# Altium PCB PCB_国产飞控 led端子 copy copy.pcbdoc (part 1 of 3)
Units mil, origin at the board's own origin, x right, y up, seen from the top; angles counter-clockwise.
Board outline 3467.18 x 2997.13 mil, 4 copper layers (Top Layer, Inner1, Inner2, Bottom Layer), stack 2.757 mil thick; 107 components, 163 nets, 527 pads, 148 vias.
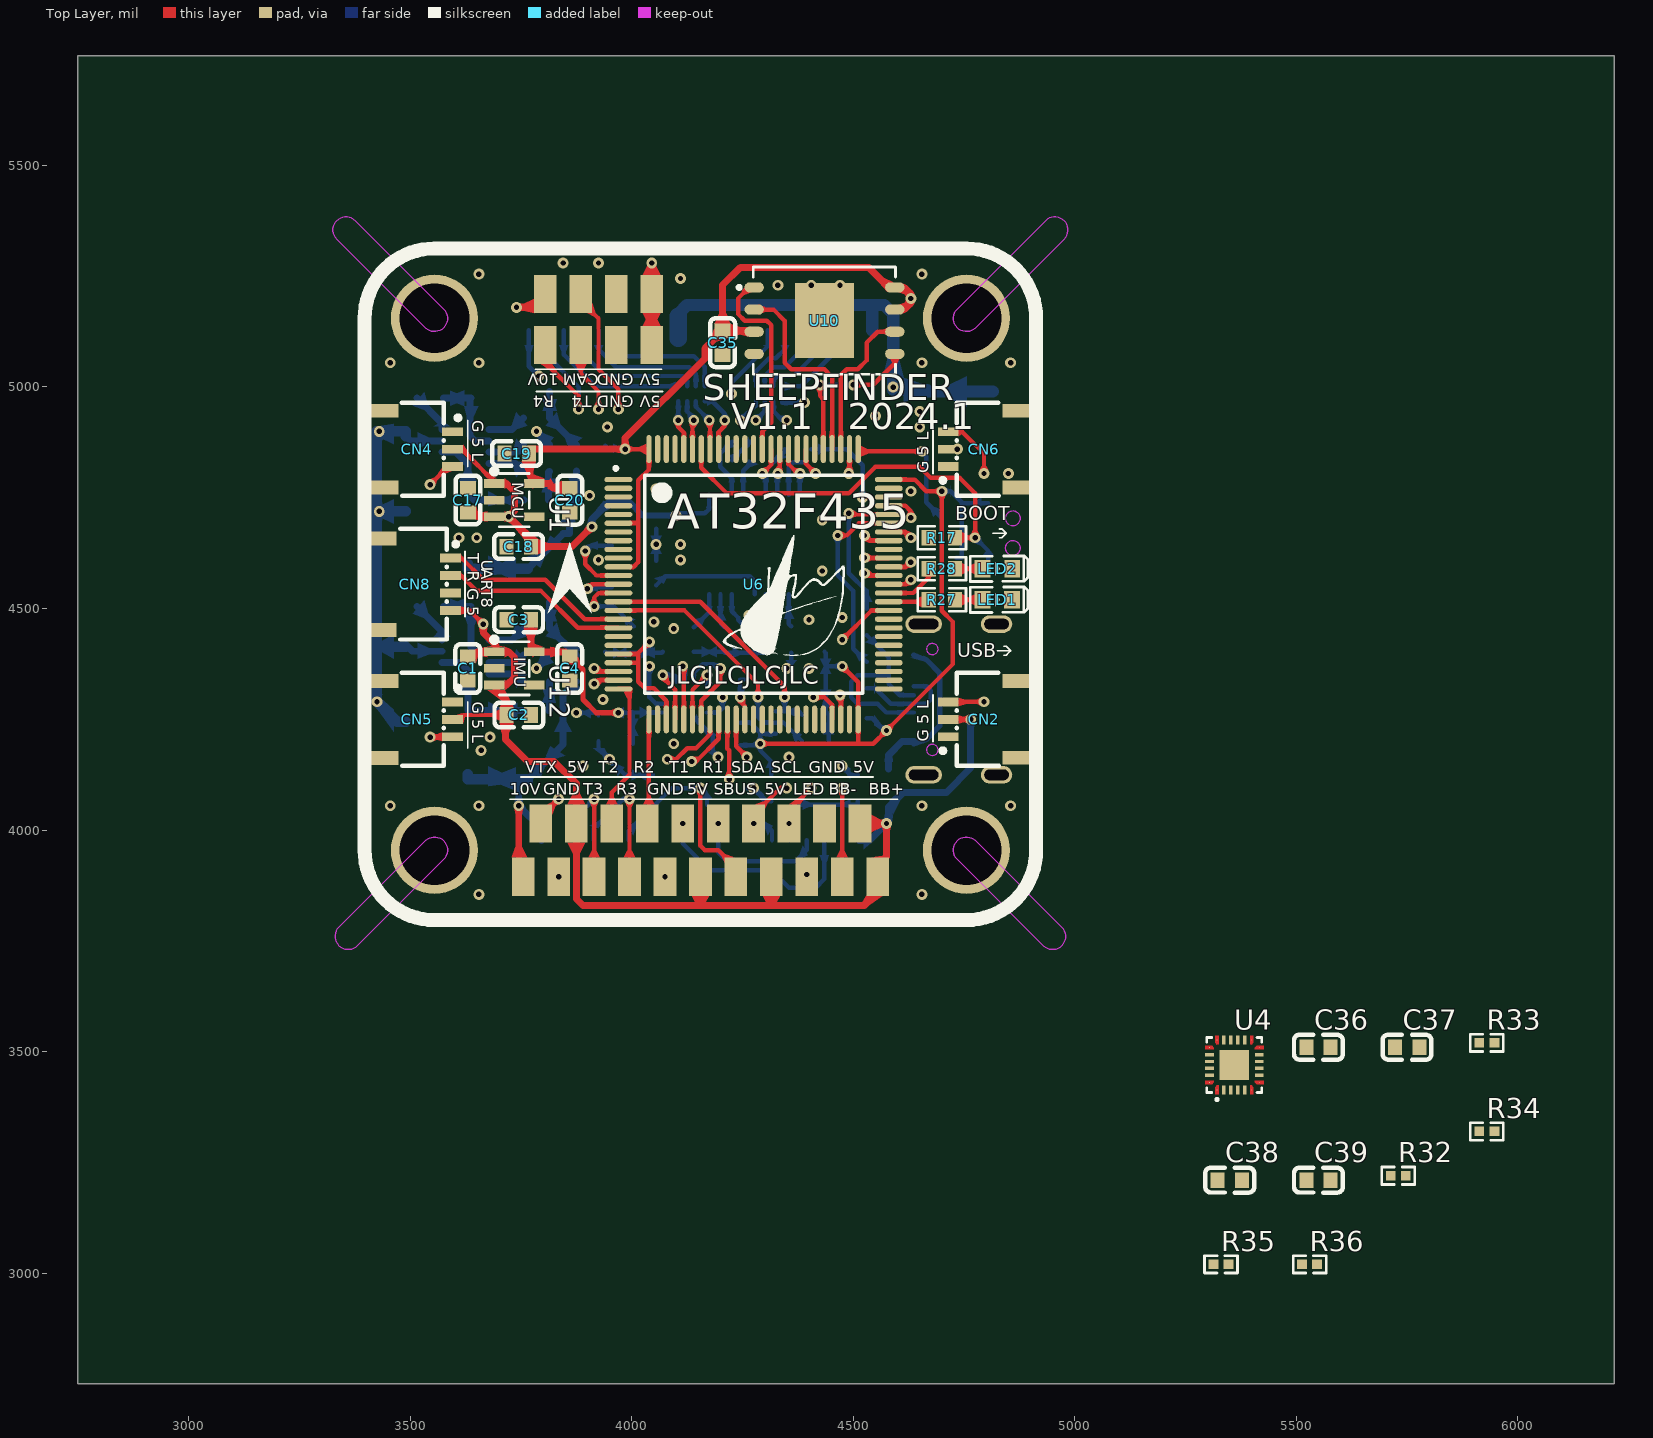
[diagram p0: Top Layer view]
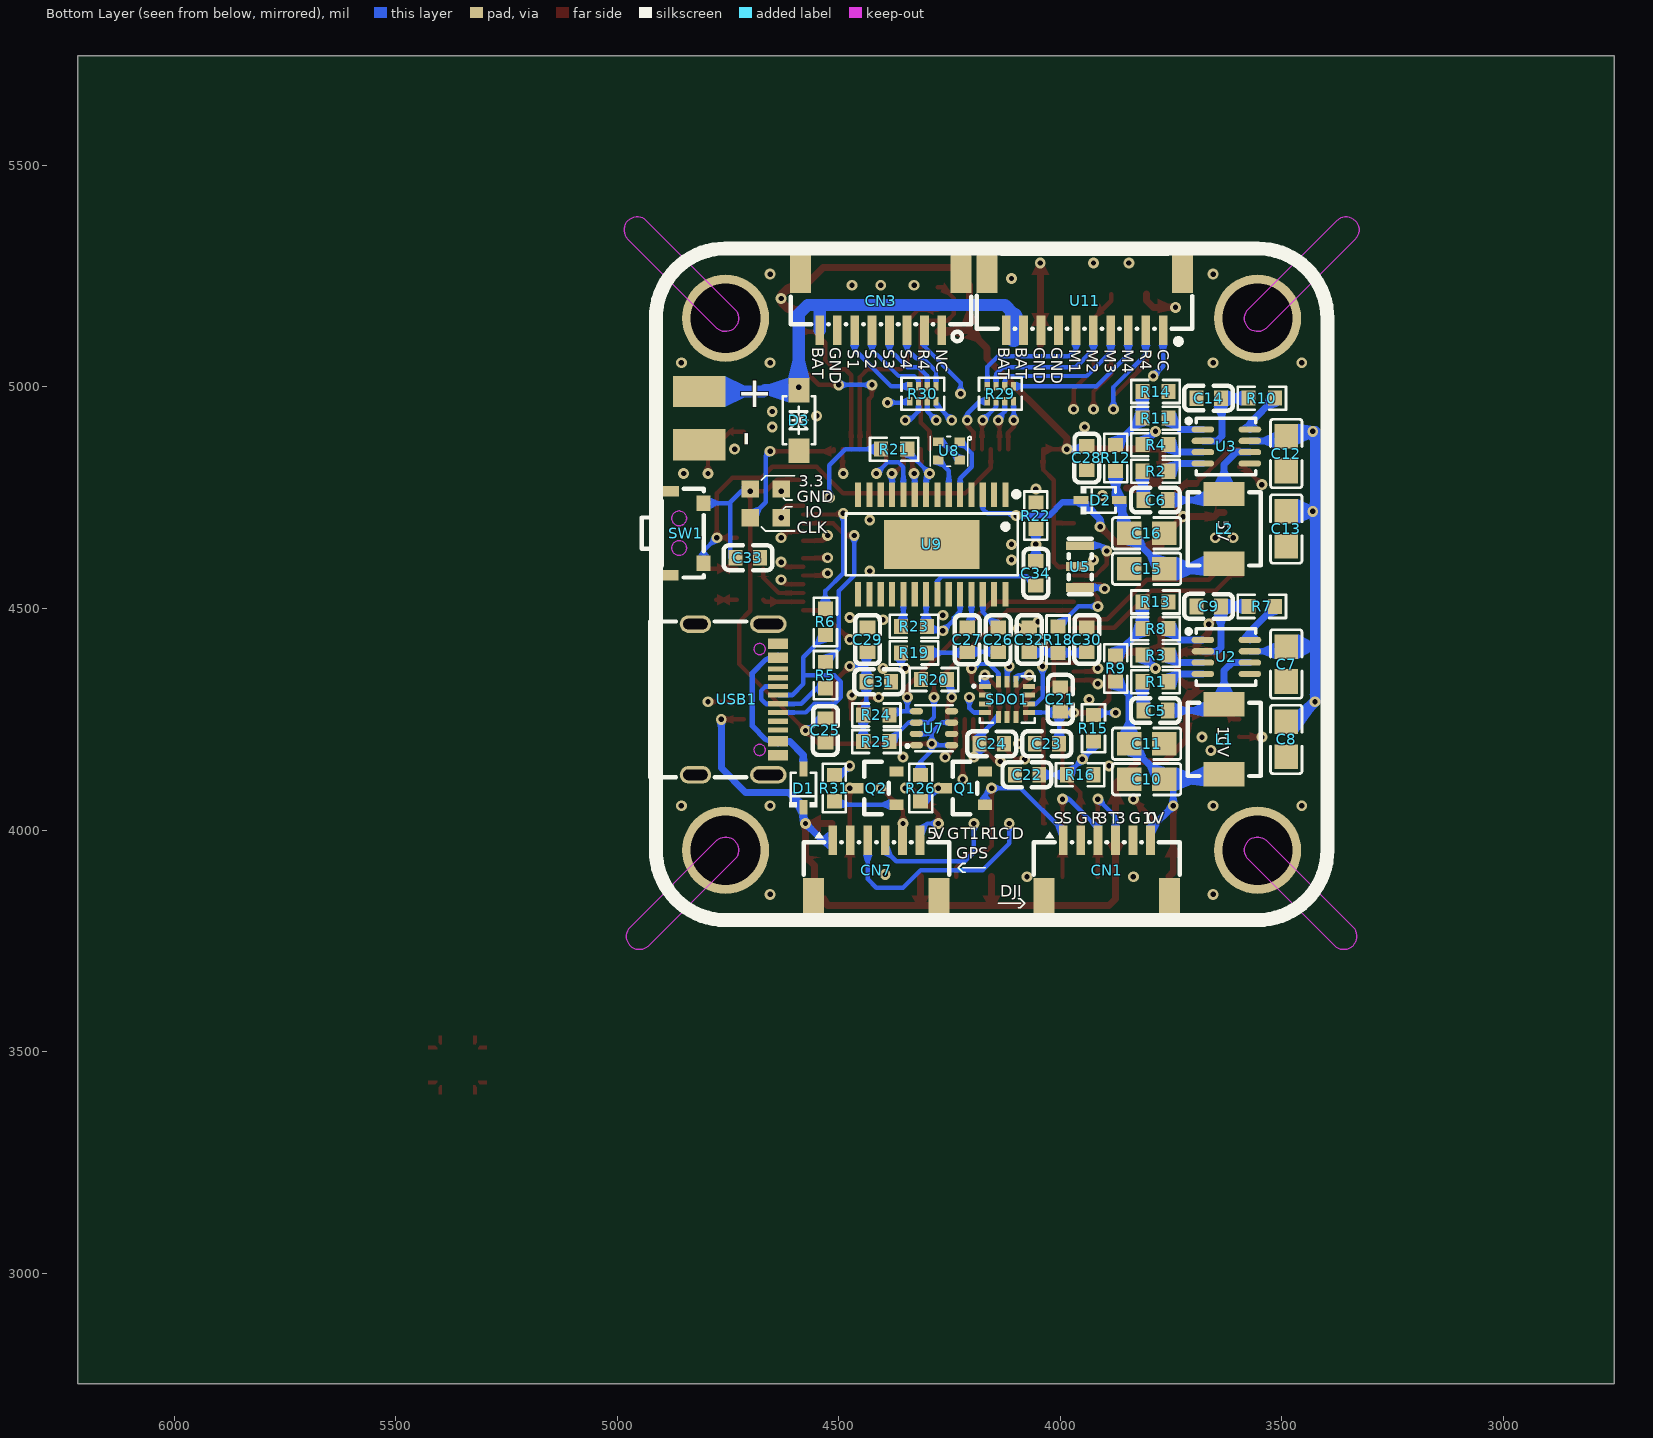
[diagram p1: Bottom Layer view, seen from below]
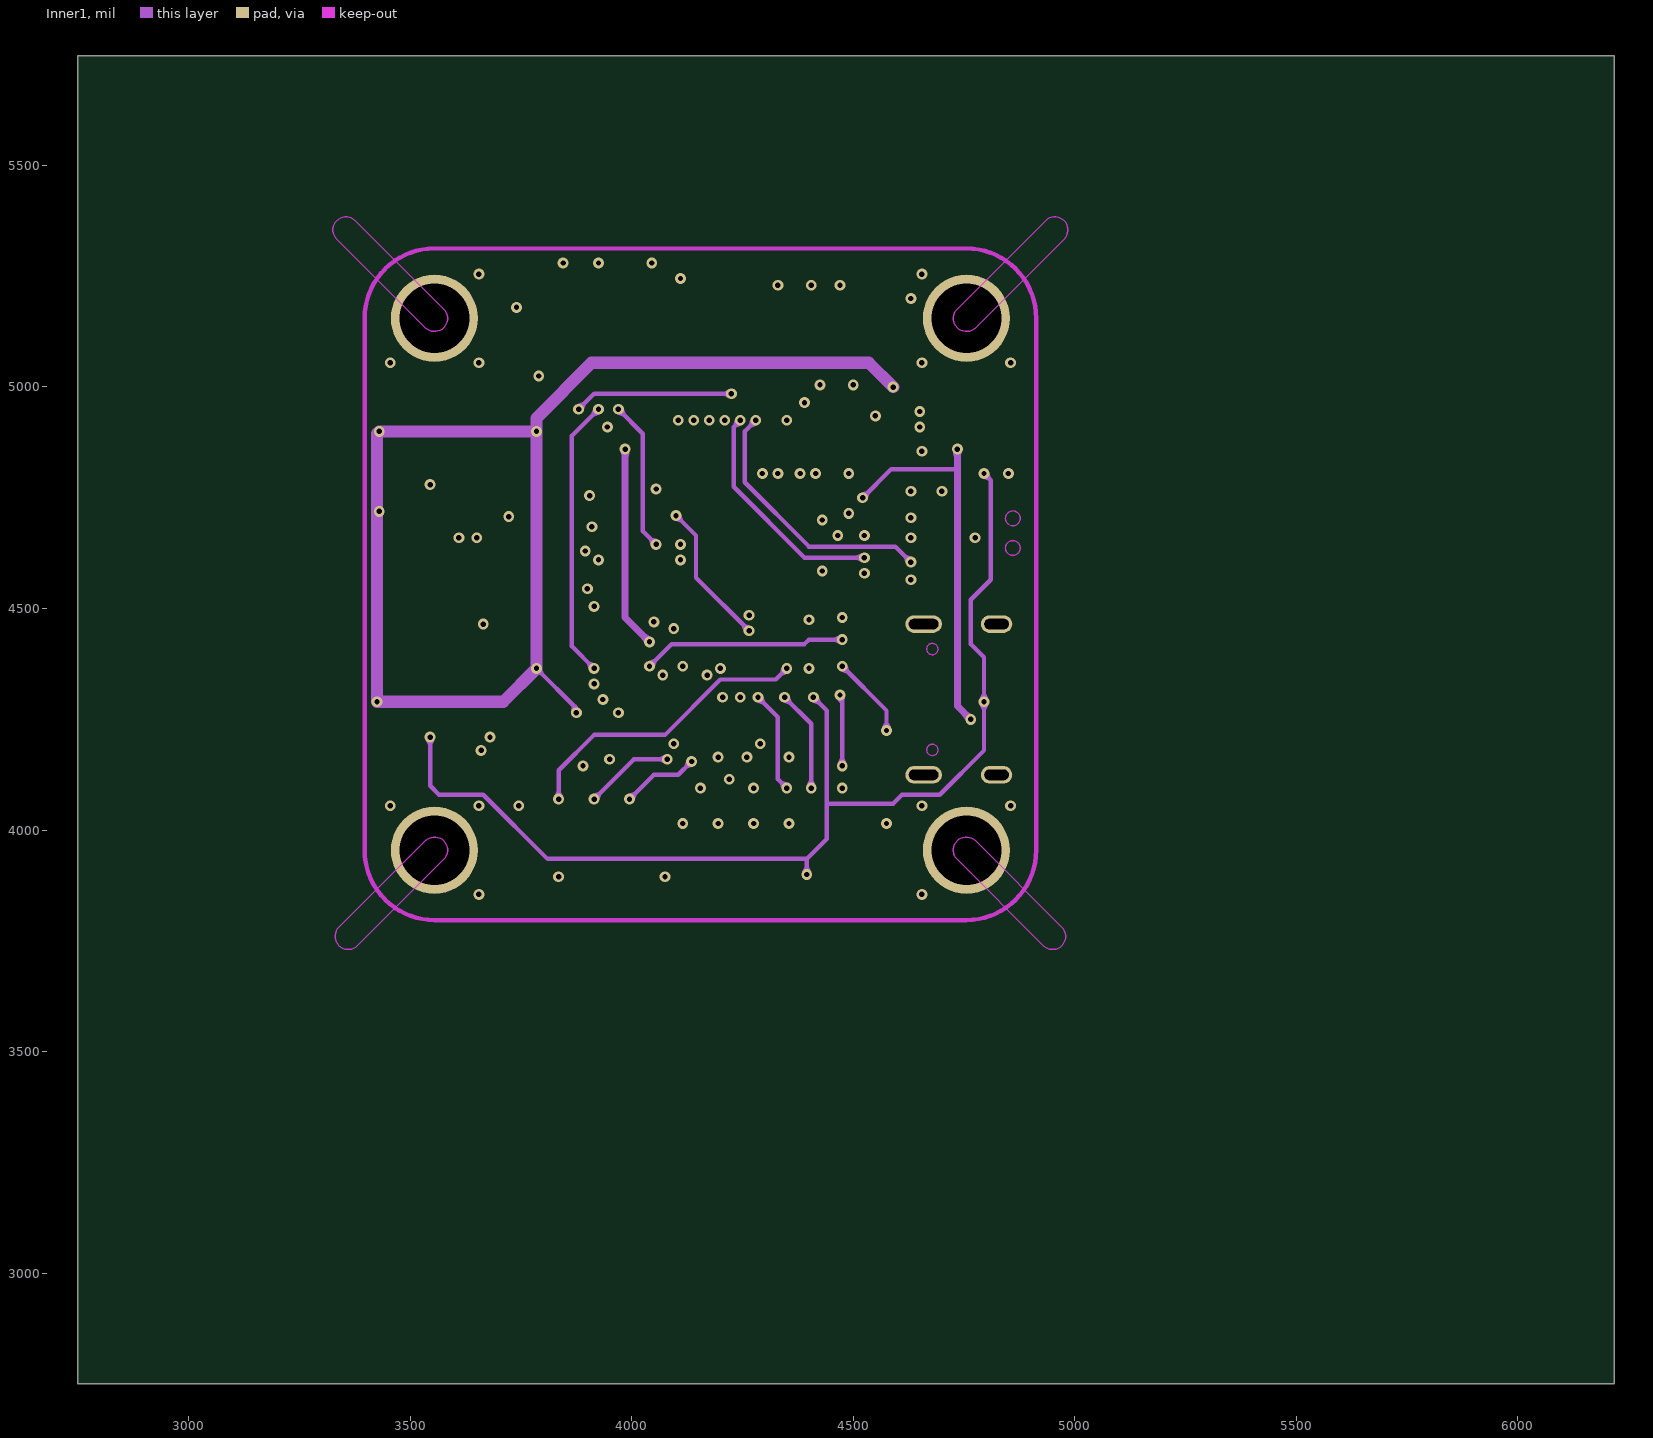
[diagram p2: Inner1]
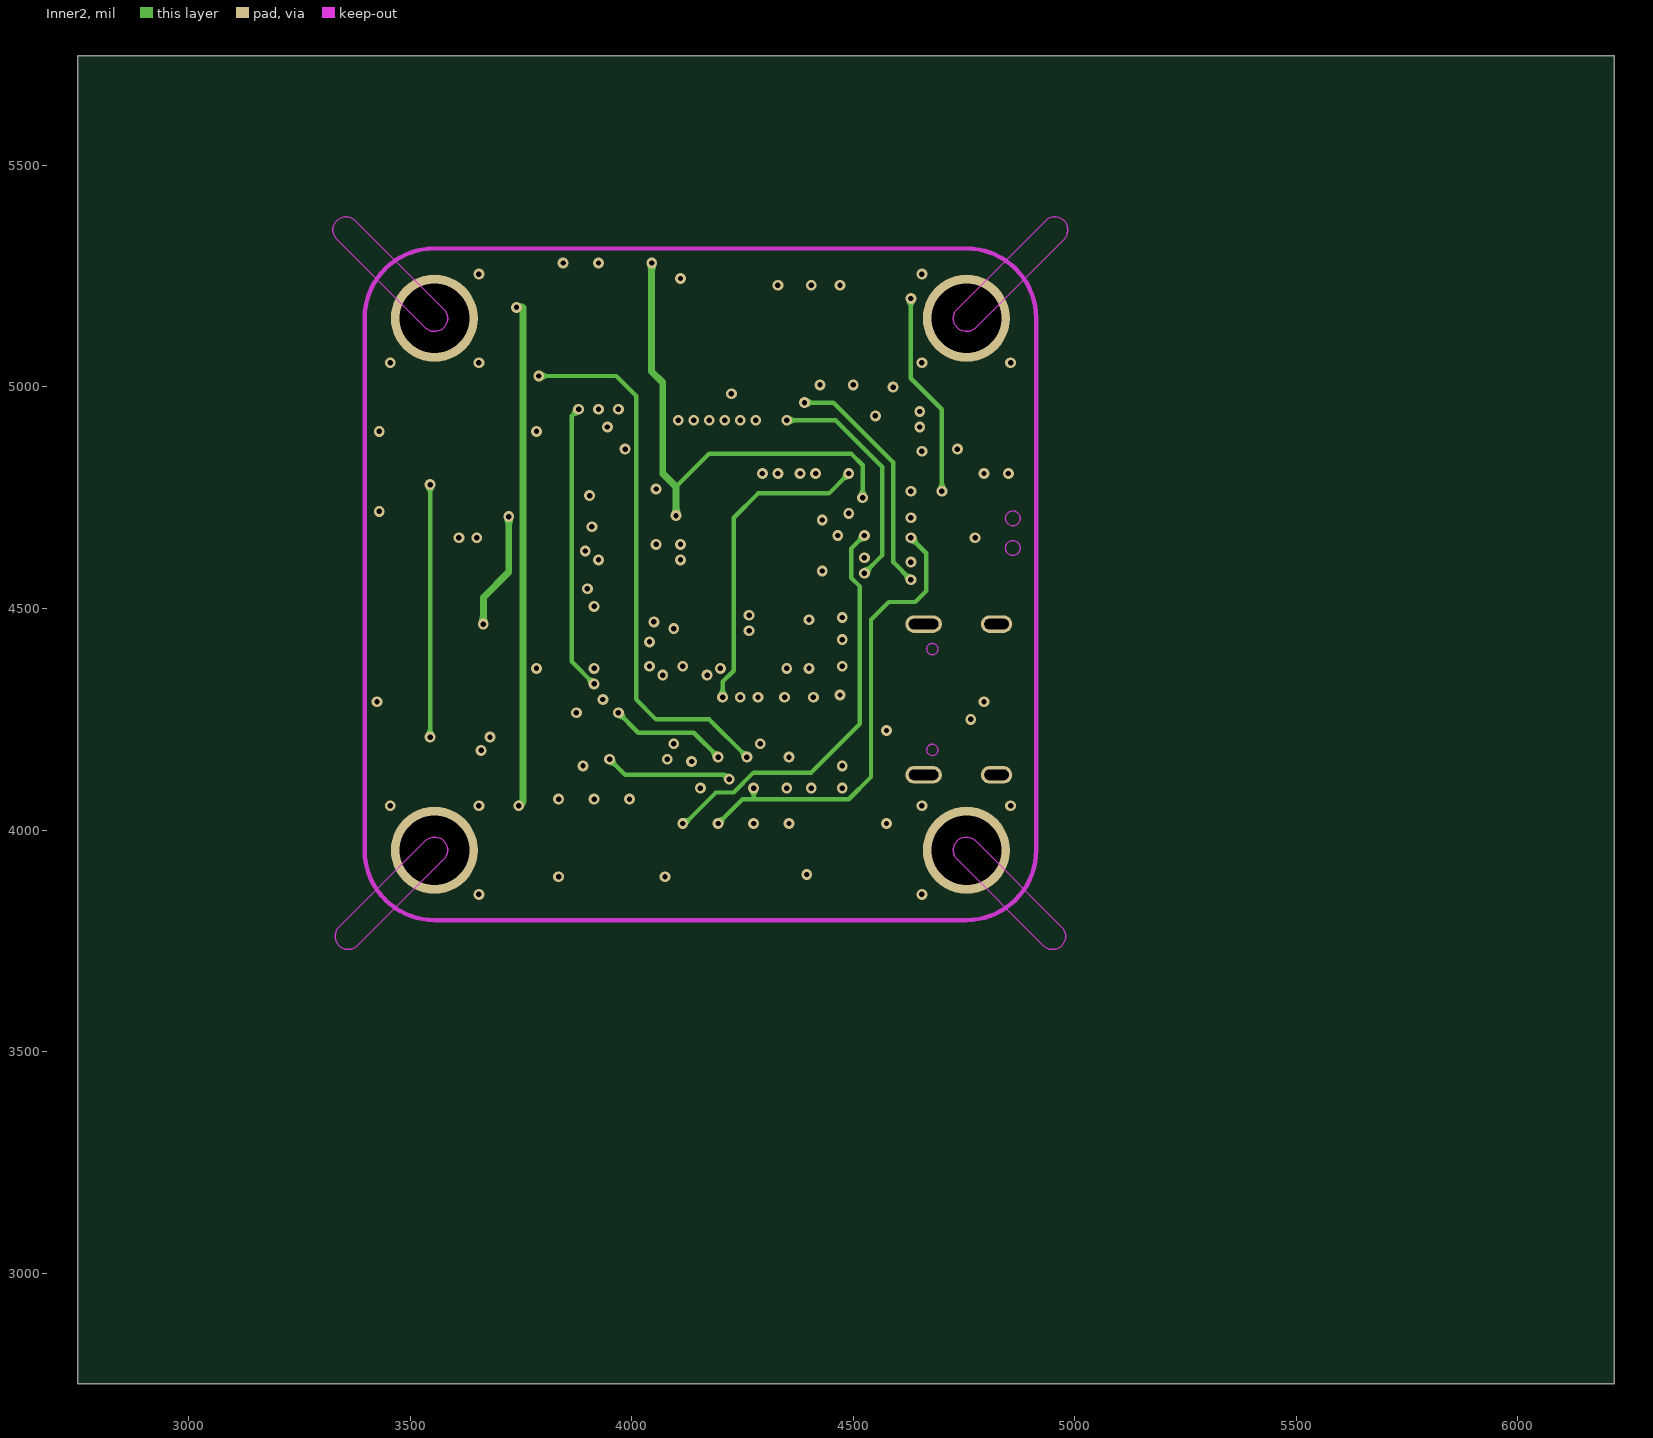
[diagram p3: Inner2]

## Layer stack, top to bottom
Top Solder Mask Layer: solder mask 0.394, Dk 3.3
Top Layer: signal copper 1.379
Inner1: signal copper (thickness not stored)
Inner2: signal copper (thickness not stored)
Bottom Layer: signal copper 1.378
Bottom Solder Mask Layer: solder mask 0.394, Dk 3.3

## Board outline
6217.18,2750 2750,2750 2750,5747.13 6217.18,5747.13

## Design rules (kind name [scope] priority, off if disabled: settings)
BoardOutlineClearance Default [All] p0: genericclearance=10 ignorepadtopadclearanceinfootprint=FALSE except(0: Arc-SplitContinuation Track-SplitContinuation SMDPad-SplitContinuation THPad-SplitContinuation Via-SplitContinuation Fill-SplitContinuation Poly-SplitContinuation Region-SplitContinuation Text-SplitContinuation)
BoardOutlineClearance otherClearance [All] p0: genericclearance=10 ignorepadtopadclearanceinfootprint=FALSE except(0: Arc-SplitContinuation Track-SplitContinuation SMDPad-SplitContinuation THPad-SplitContinuation Via-SplitContinuation Fill-SplitContinuation Poly-SplitContinuation Region-SplitContinuation Text-SplitContinuation)
Clearance Default [All] p1: gap=7 ignorepadtopadclearanceinfootprint=FALSE
Clearance otherClearance [All] p1: gap=7 ignorepadtopadclearanceinfootprint=FALSE
DiffPairsRouting differentialPair [All] p1: maxuncoupledlength=10 minlimit=5 maxlimit=Infinity mostfreqgap=6 toplayer_minwidth=5 toplayer_prefwidth=100 toplayer_maxwidth=100 bottomlayer_minwidth=5 bottomlayer_prefwidth=100 bottomlayer_maxwidth=100 midlayer1_minwidth=5 midlayer1_prefwidth=100 midlayer1_maxwidth=100 midlayer2_minwidth=5 midlayer2_prefwidth=100 midlayer2_maxwidth=100
PasteMaskExpansion pasteMaskExpansion [All] p1: expansion=0
PlaneConnect innerPlane [All] p1: planeconnectstyle=Relief reliefexpansion=20 reliefentries=4 reliefconductorwidth=10 reliefairgap=10
PolygonConnect copperRegion [All] p1: connectstyle=Relief reliefentries=4 reliefconductorwidth=10 polygonreliefangle="90 Angle" airgapwidth=10
RoutingVias Default [All] p1: viastyle="Through Hole" holewidth=12.008000000000001 minholewidth=12.008000000000001 maxholewidth=1181 width=12.008000000000001 minwidth=12.008000000000001 maxwidth=1181
SolderMaskExpansion Common [All] p1: useseparateexpansions=TRUE expansion=2 expansionbottom=2
Width Default [All] p1: maxlimit=1000 minlimit=10 preferedwidth=10

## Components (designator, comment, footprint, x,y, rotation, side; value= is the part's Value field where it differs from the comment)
C1 "100nF" C0603 3630,4364.63 r90 top
C2 "10uF" C0603 3745,4259.63 r180 top
C3 "10uF" C0603 3745,4474.63 r0 top
C4 "100nF" C0603 3860,4364.63 r90 top
C5 "100nF" C0603 3785,4269.63 r180 bottom
C6 "100nF" C0603 3785,4744.63 r180 bottom
C7 "22u" C0805 3490,4374.63 r90 bottom
C8 "22u" C0805 3490,4204.63 r90 bottom
C9 "100nF" C0603 3665,4504.63 r180 bottom
C10 "22u" C0805 3805,4114.63 r180 bottom
C11 "22u" C0805 3805,4194.63 r0 bottom
C12 "22u" C0805 3490,4849.63 r90 bottom
C13 "22u" C0805 3490,4679.63 r90 bottom
C14 "100nF" C0603 3665,4974.63 r180 bottom
C15 "22u" C0805 3805,4589.63 r180 bottom
C16 "22u" C0805 3805,4669.63 r0 bottom
C17 "100nF" C0603 3630.3,4744.63 r270 top
C18 "10uF" C0603 3744.7,4639.63 r0 top
C19 "10uF" C0603 3740.3,4849.63 r0 top
C20 "100nF" C0603 3860.3,4744.63 r90 top
C21 "10nF" C0603 4000,4294.63 r270 bottom
C22 "100nF" C0603 4075,4124.63 r180 bottom
C23 "100nF" C0603 4030,4194.63 r180 bottom
C24 "2.2uF" C0603 4155,4194.63 r0 bottom
C25 "100nF" C0603 4530,4224.63 r90 bottom
C26 "10uF" C0603 4140,4429.63 r90 bottom
C27 "10uF" C0603 4210,4429.63 r90 bottom
C28 "100nF" C0603 3940,4839.63 r90 bottom
C29 "100nF" C0603 4435,4429.63 r270 bottom
C30 "100nF" C0603 3940,4429.63 r270 bottom
C31 "100nF" C0603 4410,4334.63 r0 bottom
C32 "100nF" C0603 4070,4429.63 r270 bottom
C33 "100nF" C0603 4705,4614.63 r0 bottom
C34 "100nF" C0603 4055,4579.63 r90 bottom
C35 "100nF" C0603 4205,5099.63 r270 top
C36 "100nF" C0603 5550,3509.63 r0 top
C37 "100nF" C0603 5750,3509.63 r0 top
C38 "100nF" C0603 5350,3209.63 r0 top
C39 "2.2uF" C0603 5550,3209.63 r0 top
CN1 "SH1.0X6P" CONN-SMD_6P-P1.00_MEGASTAR_ZX-SH1.0-6PWT 3895,3909.63 r180 bottom
CN2 "SH1.0-3P" CONN-SMD_3P-P1.00_HDGC_HDGC1002WR-S-3P 4795,4249.63 r90 top
CN3 "SH1.0X8P" CONN-SMD_8P-P1.00_WAFER-SH1.0-8PWB 4405,5194.63 r0 bottom
CN4 "SH1.0-3P" CONN-SMD_3P-P1.00_HDGC_HDGC1002WR-S-3P 3515,4859.63 r270 top
CN5 "SH1.0-3P" CONN-SMD_3P-P1.00_HDGC_HDGC1002WR-S-3P 3515,4249.63 r270 top
CN6 "SH1.0-3P" CONN-SMD_3P-P1.00_HDGC_HDGC1002WR-S-3P 4795,4859.63 r90 top
CN7 "SH1.0X6P" CONN-SMD_6P-P1.00_MEGASTAR_ZX-SH1.0-6PWT 4415,3909.63 r180 bottom
CN8 "HDGC1002WR-S-4P" CONN-SMD_4P-P1.00_HDGC_HDGC1002WR-S-4P 3510,4554.63 r270 top
D1 "B5817WS-MS" SOD-323_L1.7-W1.3-LS2.7-FD 4580,4094.63 r270 bottom
D2 "B5817WS-MS" SOD-323_L1.7-W1.3-LS2.7-FD 3910,4744.63 r0 bottom
D3 "SMF28CA" SOD-123_L2.7-W1.8-LS3.7-BI 4590,4924.63 r270 bottom
L1 "10uH" IND-SMD_L4.4-W4.0_PHC0420 3630,4204.63 r270 bottom
L2 "10uH" IND-SMD_L4.4-W4.0_PHC0420 3630,4679.63 r270 bottom
LED1 "LED-0603_G" LED0603_GREEN 4825,4519.63 r0 top
LED2 "LED-0603_B" LED0603_BLUE 4825.03,4589.6 r0 top
Q1 "S8050LT1-J3Y" SOT-23_L2.9-W1.3-P1.90-LS2.4-BR 4215,4094.63 r180 bottom
Q2 "S8050LT1-J3Y" SOT-23_L2.9-W1.3-P1.90-LS2.4-BR 4415,4094.63 r180 bottom
R1 "20R" R0603 3785,4334.63 r0 bottom
R2 "20R" R0603 3785,4809.63 r0 bottom
R3 "1M" R0603 3785,4394.63 r0 bottom
R4 "1M" R0603 3785,4869.63 r0 bottom
R5 "22R" R0603 4530,4349.63 r90 bottom
R6 "22R" R0603 4530,4469.63 r90 bottom
R7 "100k" R0603 3545,4504.63 r180 bottom
R8 "51k" R0603 3785,4454.63 r0 bottom
R9 "41.2k" R0603 3875,4364.63 r270 bottom
R10 "100k" R0603 3545,4974.63 r180 bottom
R11 "51k" R0603 3785,4929.63 r0 bottom
R12 "41.2k" R0603 3875,4839.63 r270 bottom
R13 "3.6k" R0603 3785,4514.63 r0 bottom
R14 "7.68k" R0603 3785,4989.63 r0 bottom
R15 "10k" R0603 3925,4229.63 r90 bottom
R16 "1k" R0603 3955,4124.63 r0 bottom
R17 "10k" R0603 4700,4659.63 r180 top
R18 "10k" R0603 4005,4429.63 r270 bottom
R19 "75R" R0603 4330,4399.63 r0 bottom
R20 "10k" R0603 4285,4339.63 r180 bottom
R21 "10k" R0603 4375,4859.63 r180 bottom
R22 "75R" R0603 4055,4709.63 r270 bottom
R23 "10k" R0603 4330,4459.63 r180 bottom
R24 "4K7" R0603 4415,4259.63 r0 bottom
R25 "4K7" R0603 4415,4199.63 r0 bottom
R26 "1k" R0603 4315,4094.63 r90 bottom
R27 "1k" R0603 4700,4519.63 r180 top
R28 "1k" R0603 4700,4589.63 r180 top
R29 "100*4" RES-ARRAY-SMD_0402-8P-L2.0-W1.0-BL 4135,4984.63 r0 bottom
R30 "100*4" RES-ARRAY-SMD_0402-8P-L2.0-W1.0-BL 4310,4984.63 r0 bottom
R31 "1k" R0603 4510,4094.63 r270 bottom
R32 "10kΩ" R0402 5730,3219.63 r0 top
R33 "10kΩ" R0402 5930,3519.63 r0 top
R34 "10kΩ" R0402 5930,3319.63 r0 top
R35 "10kΩ" R0402 5330,3019.63 r0 top
R36 "10kΩ" R0402 5530,3019.63 r0 top
SDO1 "BMI270" LGA-14_L3.0-W2.5-P0.50-TL 4120,4294.63 r180 bottom
SW1 "TS-1073B-A2B2-D4" KEY-SMD_TS-1073B-A2B2-D4 4845,4669.63 r90 bottom
U1 "SPX3819M5-L-3-3/TR" SOT-23-5_L3.0-W1.7-P0.95-LS2.8-BL 3735,4744.63 r270 top
U2 "MP9943" QFN-8-3X3 3625,4389.63 r180 bottom
U3 "MP9943" QFN-8-3X3 3625,4864.63 r180 bottom
U4 "MPU6500" QFN-24_L3.0-W3.0-P0.40-BL-EP 5360,3469.63 r0 top
U5 "8M/3213" X3213 3955,4594.63 r90 bottom
U6 "AT32F437VMT7-LQFP100" LQFP-100_L14.0-W14.0-P0.50-LS16.0-TL 4275,4554.63 r0 top
U7 "BMP280" SENSOR-TH_BMP280-BL 4285,4229.63 r180 bottom
U8 "2016晶振/27M" 2016晶振 4250,4854.63 r0 bottom
U9 "AT7456E" TSSOP-28_L9.7-W4.4-P0.65-LS6.4-BL-EP5.5 4290,4644.63 r0 bottom
U10 "W25N01GVZEIG" WSON-8_L8.0-W6.10-P1.27-EP 4435,5149.63 r0 top
U11 "ZX-SH1.0-10PWT" CONN-SMD_10P-P1.00_ZX-SH1.0-10PWT 3945,5194.63 r0 bottom locked
U12 "SPX3819M5-L-3-3/TR" SOT-23-5_L3.0-W1.7-P0.95-LS2.8-BL 3735,4364.63 r270 top
USB1 "TYPEC-304A-16L" USB-C-SMD_XUNPU_TYPEC-304A-ACP16L 4730,4294.63 r270 bottom

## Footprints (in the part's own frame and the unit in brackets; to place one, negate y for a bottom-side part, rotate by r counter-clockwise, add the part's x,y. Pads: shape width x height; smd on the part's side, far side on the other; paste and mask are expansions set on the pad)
2016晶振 [mm]
  rect 0.6x0.5 smd: 1(-0.6,-0.55) 2(0.65,-0.55) 3(0.65,0.5) 4(-0.6,0.5)
  silkscreen extent -1.25,-0.85 1.1,0.85
C0603 [mm]
  rect 0.8x0.9 smd: 1(-0.7,0) 2(0.7,0)
  silkscreen extent -1.41,-0.71 1.39,0.72
C0805 [mm]
  rect 1.41x1.35 smd: 1(-1,0) 2(1,0)
  silkscreen extent -1.96,-0.9 1.96,0.9
CONN-SMD_3P-P1.00_HDGC_HDGC1002WR-S-3P [mm]
  rect 0.5x1.2 smd: 1(-1,2.05) 2(0,2.05) 3(1,2.05)
  rect 0.8x2 smd: 4(2.2,-2.05) 5(-2.2,-2.05)
  silkscreen extent -2.67,-2.72 2.67,2.48
CONN-SMD_4P-P1.00_HDGC_HDGC1002WR-S-4P [mm]
  rect 0.5x1.2 smd: 1(-1.5,2.05) 2(-0.5,2.05) 3(0.5,2.05) 4(1.5,2.05)
  rect 0.8x2 smd: 5(2.625,-2.05) 6(-2.625,-2.05)
  silkscreen extent -3.18,-2.72 3.17,2.49
CONN-SMD_6P-P1.00_MEGASTAR_ZX-SH1.0-6PWT [mm]
  rect 0.5x1.7 smd: 1(-2.5,1.7) 2(-1.5,1.7) 3(-0.5,1.7) 4(0.5,1.7) 5(1.5,1.7) 6(2.5,1.7)
  rect 1.2x2.5 smd: 7(3.6,-1.7) 8(-3.6,-1.7)
  silkscreen extent -4.17,-2.7 4.18,2.21
CONN-SMD_8P-P1.00_WAFER-SH1.0-8PWB [mm]
  rect 0.5x1.7 smd: 1(-3.5,1.7) 2(-2.5,1.7) 3(-1.5,1.7) 4(-0.5,1.7) 5(0.5,1.7) 6(1.5,1.7) 7(2.5,1.7) 8(3.5,1.7)
  rect 1.2x2.5 smd: 9(-4.6,-1.7) 10(4.6,-1.7)
  silkscreen extent -5.17,-2.95 5.17,2.32
CONN-SMD_10P-P1.00_ZX-SH1.0-10PWT [mm]
  rect 0.5x1.7 smd: 1(-4.5,1.7) 2(-3.5,1.7) 3(-2.5,1.7) 4(-1.5,1.7) 5(-0.5,1.7) 6(0.5,1.7) 7(1.5,1.7) 8(2.5,1.7) 9(3.5,1.7) 10(4.5,1.7)
  rect 1.2x2.5 smd: 11(5.6,-1.7) 12(-5.6,-1.7)
  silkscreen extent -6.18,-2.7 6.18,2.64
IND-SMD_L4.4-W4.0_PHC0420 [mm]
  rect 1.4x2.35 smd: 1(-2,0) 2(2,0)
  silkscreen extent -2.1,-2.1 2.1,2.1
KEY-SMD_TS-1073B-A2B2-D4 [mm]
  rect 0.9x0.8 smd: 1(-1.718,-1.013) 2(1.732,-1.013)
  rect 0.6x1.2 smd: 3(-2.407,1.013) 4(2.407,0.987)
  Board Outline Layer circle w0.003: c-0.843,0.387 r0.425
  Board Outline Layer circle w0.003: c0.857,0.387 r0.425
  Board Outline Layer region: -0.843,0.812 -1.028,0.769 -1.176,0.652 -1.258,0.481 -1.258,0.292 -1.176,0.122 -1.028,0.004 -0.843,-0.038 -0.843,-0.038 -0.659,0.004 -0.511,0.122 -0.429,0.292 -0.429,0.481 -0.511,0.652 -0.659,0.769 -0.843,0.812
  Board Outline Layer region: -0.843,0.812 -1.028,0.769 -1.176,0.652 -1.258,0.481 -1.258,0.292 -1.176,0.122 -1.028,0.004 -0.843,-0.038 -0.843,-0.038 -0.659,0.004 -0.511,0.122 -0.429,0.292 -0.429,0.481 -0.511,0.652 -0.659,0.769 -0.843,0.812
  Board Outline Layer region: 0.857,0.812 0.672,0.769 0.524,0.652 0.442,0.481 0.442,0.292 0.524,0.122 0.672,0.004 0.857,-0.038 0.857,-0.038 1.041,0.004 1.189,0.122 1.271,0.292 1.271,0.481 1.189,0.652 1.041,0.769 0.857,0.812
  Board Outline Layer region: 0.857,0.812 0.672,0.769 0.524,0.652 0.442,0.481 0.442,0.292 0.524,0.122 0.672,0.004 0.857,-0.038 0.857,-0.038 1.041,0.004 1.189,0.122 1.271,0.292 1.271,0.481 1.189,0.652 1.041,0.769 0.857,0.812
  silkscreen extent -2.53,-1.03 2.55,2.53
LED0603_BLUE [mm]
  rect 0.9x1 smd: 1(-0.85,0) 2(0.85,0)
  silkscreen extent -1.54,-0.73 1.75,0.73
LED0603_GREEN [mm]
  rect 0.9x1 smd: 1(-0.85,0) 2(0.85,0)
  silkscreen extent -1.54,-0.73 1.75,0.73
LGA-14_L3.0-W2.5-P0.50-TL [mm]
  rect 0.675x0.28 smd: 1(-1.262,0.75) 2(-1.262,0.25) 3(-1.262,-0.25) 4(-1.262,-0.75) 8(1.262,-0.75) 9(1.262,-0.25) 10(1.262,0.25) 11(1.262,0.75)
  rect 0.28x0.675 smd: 5(-0.5,-1.012) 6(0,-1.012) 7(0.5,-1.012) 12(0.5,1.012) 13(0,1.012) 14(-0.5,1.012)
  silkscreen extent -1.98,-1.33 1.58,1.33
LQFP-100_L14.0-W14.0-P0.50-LS16.0-TL [mm]
  oval 1.6x0.3 smd: 1(-7.75,6) 2(-7.75,5.5) 3(-7.75,5) 4(-7.75,4.5) 5(-7.75,4) 6(-7.75,3.5) 7(-7.75,3) 8(-7.75,2.5) 9(-7.75,2) 10(-7.75,1.5) 11(-7.75,1) 12(-7.75,0.5) 13(-7.75,0) 14(-7.75,-0.5) 15(-7.75,-1) 16(-7.75,-1.5) 17(-7.75,-2) 18(-7.75,-2.5) 19(-7.75,-3) 20(-7.75,-3.5) 21(-7.75,-4) 22(-7.75,-4.5) 23(-7.75,-5) 24(-7.75,-5.5) 25(-7.75,-6) 51(7.75,-6) 52(7.75,-5.5) 53(7.75,-5) 54(7.75,-4.5) 55(7.75,-4) 56(7.75,-3.5) 57(7.75,-3) 58(7.75,-2.5) 59(7.75,-2) 60(7.75,-1.5) 61(7.75,-1) 62(7.75,-0.5) 63(7.75,0) 64(7.75,0.5) 65(7.75,1) 66(7.75,1.5) 67(7.75,2) 68(7.75,2.5) 69(7.75,3) 70(7.75,3.5) 71(7.75,4) 72(7.75,4.5) 73(7.75,5) 74(7.75,5.5) 75(7.75,6)
  oval 0.3x1.6 smd: 26(-6,-7.75) 27(-5.5,-7.75) 28(-5,-7.75) 29(-4.5,-7.75) 30(-4,-7.75) 31(-3.5,-7.75) 32(-3,-7.75) 33(-2.5,-7.75) 34(-2,-7.75) 35(-1.5,-7.75) 36(-1,-7.75) 37(-0.5,-7.75) 38(0,-7.75) 39(0.5,-7.75) 40(1,-7.75) 41(1.5,-7.75) 42(2,-7.75) 43(2.5,-7.75) 44(3,-7.75) 45(3.5,-7.75) 46(4,-7.75) 47(4.5,-7.75) 48(5,-7.75) 49(5.5,-7.75) 50(6,-7.75) 76(6,7.75) 77(5.5,7.75) 78(5,7.75) 79(4.5,7.75) 80(4,7.75) 81(3.5,7.75) 82(3,7.75) 83(2.5,7.75) 84(2,7.75) 85(1.5,7.75) 86(1,7.75) 87(0.5,7.75) 88(0,7.75) 89(-0.5,7.75) 90(-1,7.75) 91(-1.5,7.75) 92(-2,7.75) 93(-2.5,7.75) 94(-3,7.75) 95(-3.5,7.75) 96(-4,7.75) 97(-4.5,7.75) 98(-5,7.75) 99(-5.5,7.75) 100(-6,7.75)
  silkscreen extent -8,-6.25 6.25,6.75
QFN-8-3X3 [mm]
  oval 1.3x0.35 smd: 1(-1.349,1.001) 2(-1.349,0.351) 3(-1.349,-0.3) 4(-1.349,-0.95) 5(1.346,-0.95) 6(1.346,-0.3) 7(1.346,0.351) 8(1.349,1.001)
  silkscreen extent -2.29,-1.6 1.68,1.64
QFN-24_L3.0-W3.0-P0.40-BL-EP [mm]
  round 0.04 smd: 1(-1,-1.428) 6(1,-1.428) 7(1.428,-1) 12(1.428,1) 13(1,1.428) 18(-1,1.428) 19(-1.428,1) 24(-1.428,-1)
  rect 0.2x0.505 smd: 2(-0.6,-1.428) 3(-0.2,-1.428) 4(0.2,-1.428) 5(0.6,-1.428) 14(0.6,1.428) 15(0.2,1.428) 16(-0.2,1.428) 17(-0.6,1.428)
  rect 0.505x0.2 smd: 8(1.428,-0.6) 9(1.428,-0.2) 10(1.428,0.2) 11(1.428,0.6) 20(-1.428,0.6) 21(-1.428,0.2) 22(-1.428,-0.2) 23(-1.428,-0.6)
  rect 1.7x1.7 smd: 25(0,0)
  Top Layer region: -1.1,1.68 -0.9,1.68 -0.9,1.175 -1,1.174 -1.1,1.274
  Top Layer region: -1.68,-1.1 -1.274,-1.1 -1.174,-1 -1.175,-0.9 -1.68,-0.9
  Top Layer region: 1.68,-1.1 1.275,-1.1 1.175,-1 1.175,-0.9 1.68,-0.9
  Top Layer region: 1.68,1.1 1.274,1.1 1.174,1 1.175,0.9 1.68,0.9
  Top Layer region: 1.1,1.68 0.9,1.68 0.9,1.175 1,1.174 1.1,1.274
  Top Layer region: -1.1,-1.68 -0.9,-1.68 -0.9,-1.175 -1,-1.174 -1.1,-1.275
  Top Layer region: 1.1,-1.68 0.9,-1.68 0.9,-1.175 1,-1.175 1.1,-1.275
  Top Layer region: -1.68,1.1 -1.274,1.1 -1.174,1 -1.175,0.9 -1.68,0.9
  silkscreen extent -1.58,-2.05 1.58,1.58
R0402 [mm]
  rect 0.566x0.54 smd: 1(-0.433,0) 2(0.433,0)
  silkscreen extent -0.94,-0.5 0.94,0.5
R0603 [mil]
  rect 31.75x34.02 smd: 1(-29.66,0) 2(29.66,0)
  silkscreen extent -55,-26 55,26
RES-ARRAY-SMD_0402-8P-L2.0-W1.0-BL [mm]
  rect 0.3x0.505 smd: 1(-0.75,0.427) 2(-0.25,0.427) 3(0.25,0.427) 4(0.75,0.427) 5(0.75,-0.427) 6(0.25,-0.427) 7(-0.25,-0.427) 8(-0.75,-0.427)
  silkscreen extent -1.23,-0.91 1.23,0.91
SENSOR-TH_BMP280-BL [mm]
  oval 0.767x0.364 smd: 1(-1.008,-0.975) 2(-1.008,-0.325) 3(-1.008,0.325) 4(-1.008,0.975) 5(1.009,0.975) 6(1.009,0.325) 7(1.009,-0.325) 8(1.009,-0.975)
  silkscreen extent -1.61,-1.33 1.08,1.33
SOD-123_L2.7-W1.8-LS3.7-BI [mm]
  rect 1.4x1.2 smd: 1(-1.735,0) 2(1.735,0)
  silkscreen extent -1.38,-0.93 1.38,0.93
SOD-323_L1.7-W1.3-LS2.7-FD [mm]
  rect 0.845x0.455 smd: 1(-1.098,0) 2(1.098,0)
  silkscreen extent -0.88,-0.8 1.1,0.8
SOT-23-5_L3.0-W1.7-P0.95-LS2.8-BL [mm]
  rect 0.49x1.157 smd: 1(-0.95,-1.154) 2(0,-1.154) 3(0.95,-1.154)
  rect 0.49x1.175 smd: 4(0.95,1.154) 5(-0.95,1.154)
  silkscreen extent -1.8,-1.29 1.53,0.85
SOT-23_L2.9-W1.3-P1.90-LS2.4-BR [mm]
  rect 0.8x0.6 smd: 1(1.15,-0.95) 2(1.15,0.95) 3(-1.15,0)
  silkscreen extent -0.7,-1.5 0.7,1.5
TSSOP-28_L9.7-W4.4-P0.65-LS6.4-BL-EP5.5 [mm]
  rect 0.35x1.4 smd: 1(-4.225,-2.85) 2(-3.575,-2.85) 3(-2.925,-2.85) 4(-2.275,-2.85) 5(-1.625,-2.85) 6(-0.975,-2.85) 7(-0.325,-2.85) 8(0.325,-2.85) 9(0.975,-2.85) 10(1.625,-2.85) 11(2.275,-2.85) 12(2.925,-2.85) 13(3.575,-2.85) 14(4.225,-2.85) 15(4.225,2.85) 16(3.575,2.85) 17(2.925,2.85) 18(2.275,2.85) 19(1.625,2.85) 20(0.975,2.85) 21(0.325,2.85) 22(-0.325,2.85) 23(-0.975,2.85) 24(-1.625,2.85) 25(-2.275,2.85) 26(-2.925,2.85) 27(-3.575,2.85) 28(-4.225,2.85)
  rect 5.5x2.8 smd: 29(0,0)
  silkscreen extent -5,-3.02 4.93,1.77
USB-C-SMD_XUNPU_TYPEC-304A-ACP16L [mm]
  oval 1x2.1 hole 0.6 slot 1.7 at 90 deg: 25(4.32,1.807) 28(-4.32,1.808)
  oval 1x1.8 hole 0.6 slot 1.4 at 90 deg copper offset 0,0: 26(4.32,-2.373) 27(-4.32,-2.372)
  rect 0.3x1.15 smd: A1(-3.35,2.373) A4(-2.55,2.373) A5(-1.25,2.373) A6(-0.25,2.373) A7(0.25,2.373) A8(1.25,2.373) A9(2.55,2.373) A12(3.35,2.373) B1(3.05,2.373) B4(2.25,2.373) B5(1.75,2.373) B6(0.75,2.373) B7(-0.75,2.373) B8(-1.75,2.373) B9(-2.25,2.373) B12(-3.05,2.373)
  Board Outline Layer circle w0.003: c-2.89,1.308 r0.325
  Board Outline Layer circle w0.003: c2.89,1.308 r0.325
  Board Outline Layer region: -2.89,0.983 -2.749,1.015 -2.636,1.105 -2.573,1.236 -2.573,1.38 -2.636,1.51 -2.749,1.601 -2.89,1.633 -2.89,1.633 -3.031,1.601 -3.144,1.51 -3.207,1.38 -3.207,1.236 -3.144,1.105 -3.031,1.015 -2.89,0.983
  Board Outline Layer region: -2.89,0.983 -2.749,1.015 -2.636,1.105 -2.573,1.236 -2.573,1.38 -2.636,1.51 -2.749,1.601 -2.89,1.633 -2.89,1.633 -3.031,1.601 -3.144,1.51 -3.207,1.38 -3.207,1.236 -3.144,1.105 -3.031,1.015 -2.89,0.983
  Board Outline Layer region: 2.89,0.983 3.031,1.015 3.144,1.105 3.207,1.236 3.207,1.38 3.144,1.51 3.031,1.601 2.89,1.633 2.89,1.633 2.749,1.601 2.636,1.51 2.573,1.38 2.573,1.236 2.636,1.105 2.749,1.015 2.89,0.983
  Board Outline Layer region: 2.89,0.983 3.031,1.015 3.144,1.105 3.207,1.236 3.207,1.38 3.144,1.51 3.031,1.601 2.89,1.633 2.89,1.633 2.749,1.601 2.636,1.51 2.573,1.38 2.573,1.236 2.636,1.105 2.749,1.015 2.89,0.983
  silkscreen extent -4.47,-4.97 4.47,0.54
WSON-8_L8.0-W6.10-P1.27-EP [mm]
  oval 1.115x0.581 smd: 1(-4.033,1.905) 2(-4.033,0.635) 3(-4.033,-0.635) 4(-4.033,-1.905) 5(4.033,-1.905) 6(4.033,-0.635) 7(4.033,0.635) 8(4.033,1.905)
  rect 3.4x4.3 smd: 9(0,0)
  silkscreen extent -4.99,-3.08 4.08,3.08
X3213 [mm]
  rect 0.5x1.6 smd: 1(-1.199,0) 2(0,0) 3(1.199,0)
  silkscreen extent -1.6,-0.65 1.6,0.65

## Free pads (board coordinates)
  rect 51.18x86.61 smd: 5(3755,3894.63) 5(3795,4014.63) 5(3805,5094.63) 5(3805,5209.63) 5(3835,3894.63) 5(3875,4014.63) 5(3885,5094.63) 5(3885,5209.63) 5(3915,3894.63) 5(3955,4014.63) 5(3965,5094.63) 5(3965,5209.63) 5(3995,3894.63) 5(4035,4014.63) 5(4045,5094.63) 5(4045,5209.63) 5(4075,3894.63) 5(4115,4014.63) 5(4155,3894.63) 5(4195,4014.63) 5(4235,3894.63) 5(4275,4014.63) 5(4315,3894.63) 5(4355,4014.63) 5(4395,3894.63) 5(4435,4014.63) 5(4475,3894.63) 5(4515,4014.63) 5(4555,3894.63)
  rect 39.37x39.37 smd far side: 5(4630,4704.63) 5(4630,4769.63) 5(4700,4704.63) 5(4700,4769.63)
  rect 118.11x70.87 smd far side: 5(4815,4869.63) 5(4815,4989.63)
  round 196.85 hole 157.48: 6(3554.61,5155.02) 6(3554.61,3954.24) 6(4755.39,3954.24) 6(4755.39,5155.02)

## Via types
v1: diameter 24.41, hole 12.2, Top Layer to Bottom Layer, 148 vias

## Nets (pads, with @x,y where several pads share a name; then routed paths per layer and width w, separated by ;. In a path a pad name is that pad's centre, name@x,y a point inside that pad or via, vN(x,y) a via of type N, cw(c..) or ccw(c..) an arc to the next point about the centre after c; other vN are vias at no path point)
1: pad.6@3554.61,5155.02
2: pad.6@4755.39,5155.02
3: pad.6@3554.61,3954.24
3V3-IMU: C3.2 C4.2 C21.2 C23.2 C24.2 C36.1 C37.1 C39.1 R34.2 R35.2 R36.2 SDO1.5 SDO1.8 U4.8 U4.13 U12.5 | length 911.9
  Top Layer w11.81: C4.2@3860,4392.19 3890,4362.23 3890,4294.63 3920,4264.63 v1(3970,4264.63)
  Top Layer w15.75: C3.2@3772.55,4474.63 3772.6,4415.63 3786.2,4402.03 3850.2,4402.03 C4.2@3860,4392.19
  Inner2 w10: v1(3970,4264.63) 4015,4219.63 4140,4219.63 v1(4195,4164.63)
  Bottom Layer w10: v1(3970,4264.63) 3994.1,4264.63 3994.5,4265.13 C21.2@4001.9,4265.13 ; C21.2@4000,4267.03 C21.2@4001.9,4265.13 ; C23.2@4002.45,4194.63 4002.4,4264.63 C21.2@4001.9,4265.13 ; SDO1.8@4070.32,4265.1 C21.2@4001.9,4265.13 ; SDO1.5@4139.7,4254.73 4182.6,4211.93 C24.2@4182.56,4194.63 4182.6,4177.03 v1(4195,4164.63)
4: pad.6@4755.39,3954.24
$2N1: CN3.6 R30.5 | length 202.7
  Bottom Layer w10: R30.5@4339.5,5001.43 4381.8,5001.43 4464.1,5083.73 CN3.6@4464.1,5127.73
$2N15: CN3.5 R30.6 | length 190.3
  Bottom Layer w10: R30.6@4319.8,5001.43 4319.8,5014.43 4330,5024.63 4365,5024.63 4424.7,5084.33 CN3.5@4424.68,5127.7
$2N17: CN3.4 R30.7 | length 176.2
  Bottom Layer w10: R30.7@4300.2,5001.43 4300.2,5024.83 4320,5044.63 4345,5044.63 4385.3,5084.93 CN3.4@4385.31,5127.7
$2N19: CN3.3 R30.8 | length 162.2
  Bottom Layer w10: R30.8@4280.5,5001.43 4280.5,5035.13 4310,5064.63 4325,5064.63 4345.9,5085.53 CN3.3@4345.94,5127.7
$2N21: R29.5 U11.6 | length 302.8
  Bottom Layer w10: U11.6@3964.68,5127.7 3964.7,5084.93 3980,5069.63 4140,5069.63 4164.5,5045.13 R29.5@4164.5,5001.43
$2N24: R29.6 U11.5 | length 313.9
  Bottom Layer w10: U11.5@3925.31,5127.7 3925.3,5084.33 3965,5044.63 4130,5044.63 4144.8,5029.83 R29.6@4144.8,5001.43
$2N26: R29.7 U11.4 | length 327.9
  Bottom Layer w10: U11.4@3885.94,5127.7 3885.9,5078.73 3940,5024.63 4115,5024.63 4125.2,5014.43 R29.7@4125.2,5001.43
$2N28: R29.8 U11.3 | length 343.3
  Bottom Layer w10: U11.3@3846.56,5127.7 3846.6,5073.03 3918.2,5001.43 R29.8@4105.5,5001.43
$2N34: C26.1 C27.1 R19.1 | length 162.7
  Bottom Layer w10: C26.1@4140,4402.03 4210,4402.03 4210,4399.63 R19.1@4300.34,4399.63
$2N35: C27.2 U9.25 | length 79.2
  Bottom Layer w10: U9.25@4200.43,4532.42 4200.4,4466.83 C27.2@4210,4457.19
$2N36: C26.2 U9.26 | length 89.6
  Bottom Layer w10: C26.2@4140,4457.19 4174.8,4492.03 U9.26@4174.84,4532.42
$2N52: LED2.1 R28.1 | length 61.8
  Top Layer w10: R28.1@4729.66,4589.63 LED2.1@4791.5,4589.63
$2N53: LED1.1 R27.1 | length 46.8
  Top Layer w10: R27.1@4729.66,4519.63 LED1.1@4776.5,4519.63
$2N64: R18.1 U6.14 | length 187.9
  Top Layer w10: v1(3915,4504.63) 3915,4524.63 3925.3,4534.93 U6.14@3969.89,4534.94
  Bottom Layer w10: v1(3915,4504.63) 3959.7,4504.63 R18.1@4005,4459.3
$2N83: R20.2 U6.37 | length 104.7
  Top Layer w10: v1(4245,4299.63) 4245,4290.23 4255.3,4279.93 U6.37@4255.32,4249.52
  Bottom Layer w10: v1(4245,4299.63) 4245,4339.63 R20.2@4255.34,4339.63
$2N124: U8.1 U9.5 | length 131.2
  Bottom Layer w10: U9.5@4226,4766.83 4226,4793.63 4200,4819.63 4200,4849.93 U8.1@4226.38,4876.28
$2N125: U8.3 U9.6 | length 78
  Bottom Layer w10: U9.6@4251.6,4766.83 4251.6,4810.93 U8.3@4275.6,4834.93
$2N130: R23.1 U9.19 | length 75.2
  Bottom Layer w10: U9.19@4353.98,4532.42 4354,4465.33 R23.1@4359.66,4459.63
$2N133: C34.1 U9.22 | length 265.2
  Bottom Layer w10: C34.1@4055,4552.03 4075.9,4572.93 4266.7,4572.93 4277.2,4562.43 U9.22@4277.21,4532.42
$2N182: Q2.1 R31.2 | length 147.9
  Bottom Layer w10: Q2.1@4369.8,4057.23 4510,4057.23 R31.2@4510,4064.93
$2N229: C5.2 L1.1 U2.6 | length 282.9
  Bottom Layer w15.75: U2.6@3572,4377.83 3611.8,4377.83 3630,4359.63 3630,4283.33 3630,4269.63 C5.2@3757.45,4269.63
$2N232: R8.2 R9.1 R13.2 | length 145.3
  Bottom Layer w15.75: R13.2@3814.66,4514.63 R8.2@3814.66,4454.63 R9.1@3875,4394.3
$2N233: R8.1 U2.1 | length 87.8
  Bottom Layer w15.75: U2.1@3678.1,4429.03 3729.7,4429.03 R8.1@3755.34,4454.63
$2N234: C5.1 R1.2 | length 65.9
  Bottom Layer w15.75: C5.1@3812.55,4269.63 3814.7,4271.73 R1.2@3814.66,4334.63
$2N235: R1.1 U2.4 | length 84.5
  Bottom Layer w15.75: U2.4@3678.1,4352.23 3737.7,4352.23 R1.1@3755.34,4334.63
$2N236: C9.2 R7.1 U2.2 | length 199.4
  Bottom Layer w15.75: R7.1@3574.66,4504.63 C9.2@3637.45,4504.63 3637.4,4412.23 3646.2,4403.43 U2.2@3678.1,4403.43
$2N237: R3.1 U2.3 | length 84.2
  Bottom Layer w15.75: U2.3@3678.1,4377.83 3738.5,4377.83 R3.1@3755.34,4394.63
$2N238: R7.2 U2.8 | length 99
  Bottom Layer w15.75: R7.2@3515.34,4504.63 3571.9,4448.03 U2.8@3571.9,4429.03
$2N239: R11.1 U3.1 | length 87.8
  Bottom Layer w15.75: U3.1@3678.1,4904.03 3729.7,4904.03 R11.1@3755.34,4929.63
$2N240: C14.2 R10.1 U3.2 | length 196.4
  Bottom Layer w15.75: R10.1@3574.66,4974.63 C14.2@3637.45,4974.63 3635,4972.23 3635,4889.63 3646.2,4878.43 U3.2@3678.1,4878.43
$2N241: R4.1 U3.3 | length 84.2
  Bottom Layer w15.75: U3.3@3678.1,4852.83 3738.5,4852.83 R4.1@3755.34,4869.63
$2N242: R2.1 U3.4 | length 84.5
  Bottom Layer w15.75: U3.4@3678.1,4827.23 3737.7,4827.23 R2.1@3755.34,4809.63
$2N244: C6.2 L2.1 U3.6 | length 269.1
  Bottom Layer w15.75: U3.6@3572,4852.83 3601.8,4852.83 3630,4824.63 3630,4758.33 3643.7,4744.63 C6.2@3757.45,4744.63
$2N246: R10.2 U3.8 | length 94
  Bottom Layer w15.75: R10.2@3515.34,4974.63 3571.9,4918.03 U3.8@3571.9,4904.03
$2N247: C6.1 R2.2 | length 65.9
  Bottom Layer w15.75: C6.1@3812.55,4744.63 3812.6,4807.53 R2.2@3814.66,4809.63
$2N248: R11.2 R12.1 R14.2 | length 145.3
  Bottom Layer w15.75: R14.2@3814.66,4989.63 R11.2@3814.66,4929.63 R12.1@3875,4869.3
$2N249: C15.2 C16.2 D2.1 L2.2 R12.2 | length 426.5
  Bottom Layer w15.75: C15.2@3765.63,4589.63 3844.4,4668.33 C16.2@3844.37,4669.63 3860,4669.63 3860,4737.83 D2.1@3866.79,4744.63 3875,4744.63 R12.2@3875,4809.93
  Bottom Layer w23.62: L2.2@3630,4600.89 3630,4589.63 C15.2@3765.63,4589.63
$2N284: U4.1
$2N285: U4.2
$2N286: U4.3
$2N287: U4.4
$2N288: U4.5
$2N289: U4.6
$2N290: U4.7
$2N293: C38.2 U4.10
$2N294: R32.2 U4.11
$2N297: U4.14
$2N298: U4.15
$2N299: U4.16
$2N300: U4.17
$2N302: U4.19
$2N303: U4.21
+5V: C1.2 C2.2 C17.2 C18.2 CN2.2 CN4.2 CN5.2 CN6.2 CN7.1 CN8.4 D1.2 D2.2 pad.5@3875,4014.63 pad.5@4045,5094.63 pad.5@4045,5209.63 pad.5@4155,3894.63 pad.5@4315,3894.63 pad.5@4515,4014.63 pad.5@4555,3894.63 R21.1 R23.2 U1.1 U1.3 U9.3 U9.21 U9.24 U12.1 U12.3 | length 6826.7
  Top Layer w10: CN5.2@3595.71,4249.63 3610,4249.63 3620,4259.63 C2.2@3717.45,4259.63 ; CN4.2@3595.71,4859.63 3616.2,4859.63 U1.1@3693.8,4782.03 ; CN2.2@4714.29,4249.63 v1(4765,4249.63)
  Top Layer w10.04: CN8.4@3590.7,4495.53 3634.1,4495.53 v1(3665,4464.63)
  Top Layer w15.75: C1.2@3630,4392.19 3642.6,4392.23 3652.4,4402.03 U12.1@3683.8,4402.03 ; C17.2@3630.3,4717.03 3642.6,4717.03 3652.4,4707.23 3683.5,4707.23 3722.6,4707.23 3735,4719.63 3735,4764.63 3717.6,4782.03 U1.1@3693.8,4782.03 ; v1(3665,4464.63) 3665,4444.63 3693.5,4416.13 3693.5,4402.03 3722.6,4402.03 3735,4389.63 3735,4344.63 3717.6,4327.23 3693.5,4327.23 3693.5,4316.13 3717.5,4292.13 3717.5,4259.63 3715,4257.13 3715,4204.63 3765,4154.63 3825,4154.63 3875,4104.63 pad.5@3875,4014.63 3875,3844.63 3890,3829.63 4155,3829.63 ; U1.3@3693.8,4707.23 v1(3722.4,4707.23) 3772.3,4657.33 3772.3,4639.63 3865,4639.63 v1(3910,4684.63) ; pad.5@4045,5094.63 pad.5@4045,5209.63 4045,5234.63 v1(4045,5279.63) ; pad.5@4155,3894.63 4155,3829.63 ; 4315,3829.63 pad.5@4315,3894.63 ; pad.5@4515,4014.63 v1(4575,4014.63) 4575,3939.63 4555,3919.63 pad.5@4555,3894.63 4555,3859.63 4525,3829.63 4155,3829.63
  Inner1 w10: v1(4100,4709.63) 4145,4664.63 4145,4569.63 v1(4265,4449.63) ; v1(4521.06,4749.7) 4586,4814.63 4735,4814.63 v1(4735,4859.63)
  Inner1 w15.75: v1(4735,4859.63) 4735,4279.63 v1(4765,4249.63)
  Inner2 w10.08: 4100,4774.63 4175,4849.63 4495,4849.63 4521.1,4823.53 v1(4521.06,4749.7)
  Inner2 w15.75: v1(3665,4464.63) 3665,4524.63 3722.4,4582.03 v1(3722.4,4707.23) ; v1(4045,5279.63) 4045,5034.63 4070,5009.63 4070,4804.63 4100,4774.63 v1(4100,4709.63)
  Bottom Layer w10: v1(4100,4709.63) 4105,4714.63 4165,4714.63 4174.8,4724.43 U9.3@4174.84,4756.83 ; U9.24@4226.02,4532.42 4226,4493.63 4240,4479.63 4240,4474.63 v1(4265,4449.63) 4290.3,4449.63 R23.2@4300.34,4459.63 4302.8,4459.63 U9.21@4302.8,4532.42 ; R21.1@4404.66,4859.63 4485,4859.63 4521.1,4823.53 v1(4521.06,4749.7)
  Bottom Layer w13.78: D2.2@3955,4739.63 3995,4739.63 4025,4709.63 v1(4100,4709.63)
  Bottom Layer w15.75: v1(3910,4684.63) 3910,4701.43 D2.2@3953.21,4744.63 ; CN7.1@4513.4,3976.53 4536.9,3976.53 v1(4575,4014.63) 4580,4019.63 D1.2@4580,4051.42 4613.2,4084.63 4710,4084.63 4765,4139.63 v1(4765,4249.63)
+10V: C10.2 C11.2 CN1.6 L1.2 pad.5@3755,3894.63 pad.5@3805,5209.63 R9.2 | length 1973.6
  Top Layer w15.75: v1(3740,5179.63) 3790,5179.63 3805,5194.63 pad.5@3805,5209.63 ; v1(3745,4054.63) 3745,3904.63 pad.5@3755,3894.63
  Inner2 w15.75: v1(3740,5179.63) 3755,5179.63 3755,4064.63 v1(3745,4054.63)
  Bottom Layer w15.75: C10.2@3740,4114.63 3745,4109.63 v1(3745,4054.63) 3796.6,4003.03 CN1.6@3796.6,3976.53 ; C10.2@3765.63,4114.63 3844.4,4193.33 C11.2@3844.37,4194.63 3844.4,4304.33 R9.2@3875,4334.93
  Bottom Layer w23.62: L1.2@3630,4125.89 3630,4114.63 3740,4114.63 C10.2@3765.63,4114.63 ; C10.2@3765.6,4109.63 C10.2@3765.63,4114.63
AT_CS: R21.2 U6.86 U9.8 | length 180
  Top Layer w10: v1(4295,4804.63) 4314.4,4824.03 U6.86@4314.37,4859.74
  Bottom Layer w10: U9.8@4302.8,4766.83 4302.8,4796.83 v1(4295,4804.63) 4345.3,4854.93 R21.2@4345.34,4859.63
AT_MISO: U6.84 U9.11 | length 117.1
  Top Layer w10: U6.84@4353.74,4859.74 4353.7,4825.93 4375,4804.63 v1(4380,4804.63)
  Bottom Layer w10: U9.11@4379.57,4756.83 4379.6,4804.63 v1(4380,4804.63)
AT_MOSI: U6.85 U9.9 | length 105.3
  Top Layer w10: v1(4330,4804.63) 4334.1,4808.73 U6.85@4334.06,4859.74
  Bottom Layer w10: U9.9@4328.39,4756.83 4328.4,4803.03 v1(4330,4804.63)
AT_SCK: U6.82 U9.10 | length 201.9
  Top Layer w10: U6.82@4393.11,4859.74 4393.1,4826.53 v1(4415,4804.63)
  Bottom Layer w10: U9.10@4353.98,4756.83 4354,4818.63 4365,4829.63 4390,4829.63 v1(4415,4804.63)
BB: pad.5@4475,3894.63 Q2.3 | length 214.8
  Top Layer w10: pad.5@4475,3894.63 v1(4475,4094.63)
  Bottom Layer w10: Q2.3@4460.25,4094.63 v1(4475,4094.63)
BEEPER: R31.1 U6.48 | length 261.4
  Top Layer w10: v1(4470,4304.63) 4471.9,4302.73 U6.48@4471.9,4249.53
  Inner1 w10: v1(4470,4304.63) 4475,4299.63 v1(4475,4144.63)
  Bottom Layer w10: v1(4475,4144.63) 4495.3,4124.33 R31.1@4510,4124.3
BOOT0: R17.1 SW1.1 U6.94 | length 949.2
  Top Layer w10: R17.1@4729.66,4659.63 v1(4775,4659.63)
  Top Layer w10.08: U6.94@4156.89,4859.74 4156.9,4817.73 4215,4759.63 4490,4759.63 4550,4819.63 4650,4819.63 4675,4794.63 4740,4794.63 4775,4759.63 v1(4775,4659.63)
  Bottom Layer w10: v1(4775,4659.63) 4805.1,4629.53 SW1.1@4805.11,4601.98
BOX_CS: U6.87 U10.1 | length 455.2
  Top Layer w10: U10.1@4276.23,5224.63 4265,5224.63 4240,5199.63 4240,5164.63 4255,5149.63 4305,5149.63 4315,5139.63 4315,4919.63 4294.7,4899.33 U6.87@4294.69,4859.74
BOX_MISO: U6.79 U10.2 | length 457.4
  Top Layer w10: U10.2@4276.23,5174.63 4320,5174.63 4345,5149.63 4345,5054.63 4360,5039.63 4435,5039.63 4452.2,5022.43 U6.79@4452.17,4859.74
BOX_MOSI: U6.80 U10.5 | length 358.2
  Top Layer w10: v1(4425,5004.63) 4425,4979.63 4432.5,4972.13 U6.80@4432.48,4859.74 ; v1(4500,5004.63) 4545,5004.63 4593.8,5053.43 U10.5@4593.77,5074.63
  Bottom Layer w10: v1(4425,5004.63) v1(4500,5004.63)
BOX_SCK: U6.78 U10.6 | length 352.8
  Top Layer w10: U6.78@4471.9,4859.73 4471.9,5026.53 4485,5039.63 4510,5039.63 4530,5059.63 4530,5099.63 4555,5124.63 U10.6@4593.77,5124.63
C6_1: 
C26_2: 
C27_1: 
C27_2: 
CURRENT1: U6.36 U11.1 | length 1434.8
  Top Layer w10: U6.36@4235.63,4249.52 4235.6,4189.03 v1(4260,4164.63)
  Inner2 w10: v1(3790,5024.63) 3965,5024.63 4010,4979.63 4010,4294.63 4055,4249.63 4175,4249.63 v1(4260,4164.63)
  Bottom Layer w10: U11.1@3767.82,5127.7 3767.8,5046.83 v1(3790,5024.63)
D+: R6.2 U6.71 | length 323
  Top Layer w10: v1(4490,4714.63) 4492.5,4712.13 U6.71@4580.11,4712.11
  Bottom Layer w10: v1(4490,4714.63) 4490,4579.63 4530,4539.63 R6.2@4530,4499.3
D-: R5.2 U6.70 | length 438.8
  Top Layer w10: v1(4465,4664.63) 4485,4664.63 4512.8,4692.43 U6.70@4580.11,4692.43
  Bottom Layer w10: v1(4465,4664.63) 4465,4574.63 4500,4539.63 4500,4409.33 R5.2@4530,4379.3
DN: R5.1 USB1.A7 USB1.B7 | length 225.7
  Bottom Layer w10: R5.1@4530,4319.93 4549.7,4319.93 4584.8,4284.83 USB1.A7@4636.59,4284.79 4664.8,4284.83 4675,4295.03 4675,4314.63 4665.5,4324.13 USB1.B7@4636.6,4324.13
DP: R6.1 USB1.A6 USB1.B6 | length 480
  Bottom Layer w10: R6.1@4530,4439.93 4580,4389.93 4580,4329.63 4605.2,4304.43 USB1.A6@4636.6,4304.43 ; 4580,4349.23 4509.6,4349.23 4495,4334.63 4495,4299.63 4510,4284.63 4555,4284.63 4574.5,4265.13 USB1.B6@4636.59,4265.1
GND: C1.1 C2.1 C3.1 C4.1 C7.1 C8.1 C9.1 C10.1 C11.1 C12.1 C13.1 C14.1 C15.1 C16.1 C17.1 C18.1 C19.1 C20.1 C21.1 C22.1 C23.1 C24.1 C25.1 C28.1 C29.1 C30.1 C31.1 C32.1 C33.1 C35.2 C36.2 C37.2 C38.1 C39.2 CN1.2 CN1.5 CN1.7 CN1.8 CN2.1 CN2.4 CN2.5 CN3.7 CN3.9 CN3.10 CN4.1 CN4.4 CN4.5 CN5.1 CN5.4 CN5.5 CN6.1 CN6.4 CN6.5 CN7.2 CN7.7 CN7.8 CN8.3 CN8.5 CN8.6 D3.2 LED1.2 LED2.2 pad.5@3835,3894.63 pad.5@3965,5094.63 pad.5@3965,5209.63 pad.5@4075,3894.63 pad.5@4435,4014.63 pad.5@4630,4769.63 pad.5@4815,4869.63 Q1.2 Q2.2 R13.1 R14.1 R16.1 R17.2 R20.1 R22.1 R32.1 R33.1 SDO1.6 SDO1.7 U1.2 U2.5 U3.5 U4.18 U4.20 U4.25 U5.2 U6.10 U6.20 U6.27 U6.74 U6.99 U7.1 U7.5 U7.7 U8.2 U8.4 U9.4 U9.20 U9.23 U10.4 U10.9 U11.7 U11.8 U11.11 U11.12 U12.2 USB1.25 USB1.26 USB1.27 USB1.28 USB1.A1 USB1.A12 USB1.B1 USB1.B12 | length 66.4
  Bottom Layer w10: U8.4@4226.38,4834.94 4267.7,4876.33 U8.2@4275.59,4876.28
  other v1: 3655,3854.63 4655,3854.63 3835,3894.63 4075,3894.63 3455,4054.63 3655,4054.63 4655,4054.63 4855,4054.63 3890,4144.63 4355,4164.63 3660,4179.63 4095,4194.63 3680,4209.63 3935,4294.63 4400,4364.63 4095,4454.63 4050,4469.63 4400,4474.63 4475,4479.63 4265,4484.63 4430,4584.63 3925,4609.63 4110,4609.63 4110,4644.63 3610,4659.63 3650,4659.63 4430,4699.63 3905,4754.63 4630,4764.63 4055,4769.63 4850,4804.63 3945,4909.63 4650,4909.63 4550,4934.63 4650,4944.63 3455,5054.63 3655,5054.63 4655,5054.63 4855,5054.63 4330,5229.63 4405,5229.63 4470,5229.63 4110,5244.63 3655,5254.63 4655,5254.63 3845,5279.63 3925,5279.63
GYRO_CS1: R36.1 SDO1.12 U4.22 U6.29 | length 153.9
  Top Layer w10: v1(4070,4349.63) 4070,4344.63 4097.8,4316.83 U6.29@4097.83,4249.52
  Bottom Layer w10: v1(4070,4349.63) 4095,4349.63 4100.3,4344.33 SDO1.12@4100.31,4334.49
GYRO_EXTI1: SDO1.4 U4.12 U6.77 | length 837.6
  Top Layer w10: v1(4490,4804.63) 4491.5,4804.63 U6.77@4491.54,4859.74
  Inner2 w10: v1(4205,4299.63) 4205,4334.63 4230,4359.63 4230,4704.63 4285,4759.63 4445,4759.63 v1(4490,4804.63)
  Bottom Layer w10: SDO1.4@4169.69,4265.1 4195.5,4265.13 4205,4274.63 v1(4205,4299.63)
GYRO_EXTI2: SDO1.9 U6.60 | length 698.7
  Top Layer w10: v1(4475,4429.63) 4540.9,4495.53 U6.60@4580.1,4495.53
  Inner1 w10: v1(4040,4369.63) 4090,4419.63 4390,4419.63 4400,4429.63 v1(4475,4429.63)
  Bottom Layer w10: v1(4040,4369.63) 4040,4299.63 4054.8,4284.83 SDO1.9@4070.32,4284.79
GYRO_MISO: R33.2 SDO1.1 U4.9 U6.31 | length 139.3
  Top Layer w10: U6.31@4137.2,4249.52 4137.2,4316.83 v1(4170,4349.63)
  Bottom Layer w10: SDO1.1@4169.7,4324.13 4170,4324.43 v1(4170,4349.63)
GYRO_MOSI: R34.1 SDO1.14 U4.24 U6.32 | length 225.6
  Top Layer w10: U6.32@4156.89,4249.52 4156.9,4291.53 4200,4334.63 v1(4200,4364.63)
  Bottom Layer w10: SDO1.14@4139.69,4334.49 4139.7,4354.33 4160,4374.63 4185,4374.63 4195,4364.63 v1(4200,4364.63)
GYRO_SCK: R35.1 SDO1.13 U4.23 U6.30 | length 161.2
  Top Layer w10: v1(4115,4369.63) 4117.5,4367.13 U6.30@4117.52,4249.52
  Bottom Layer w10: v1(4115,4369.63) 4120,4369.63 SDO1.13@4120,4334.49
HEXT_IN: U5.3 U6.12 | length 180.4
  Top Layer w10: v1(3895,4629.63) 3895,4599.63 3920.3,4574.33 U6.12@3969.89,4574.31
  Bottom Layer w10: v1(3895,4629.63) 3907.2,4641.83 U5.3@3955,4641.83
HEXT_OUT: U5.1 U6.13 | length 131.8
  Top Layer w10: v1(3900,4544.63) 3910,4554.63 U6.13@3969.89,4554.63
  Bottom Layer w10: v1(3900,4544.63) 3900,4547.43 U5.1@3955,4547.43
I2C_SCL: CN7.5 pad.5@4355,4014.63 R24.1 U6.15 U7.4 | length 945.5
  Top Layer w10: U6.15@3969.9,4515.23 4154.4,4515.23 4345,4324.63 v1(4345,4299.63) ; v1(4355,4014.63) 4355,4044.63 v1(4405,4094.63)
  Inner1 w10: v1(4345,4299.63) 4405,4239.63 v1(4405,4094.63)
  Bottom Layer w10: U7.4@4324.7,4268.02 4377,4268.03 R24.1@4385.34,4259.63 ; v1(4345,4299.63) 4345,4273.03 4350,4268.03 ; v1(4355,4014.63) CN7.5@4355.9,3976.53
I2C_SDA: CN7.6 pad.5@4275,4014.63 R25.1 U6.16 U7.3 | length 1003.7
  Top Layer w10: U6.16@3969.9,4495.53 4119.1,4495.53 4285,4329.63 v1(4285,4299.63) ; v1(4275,4014.63) 4275,4034.63 4335,4094.63 v1(4350,4094.63)
  Inner1 w10: v1(4285,4299.63) 4330,4254.63 4330,4114.63 v1(4350,4094.63)
  Bottom Layer w10: v1(4275,4014.63) 4300,4014.63 4316.6,3998.03 CN7.6@4316.6,3976.53 ; v1(4285,4299.63) 4285,4254.63 4297.2,4242.43 U7.3@4324.7,4242.43 4342.5,4242.43 R25.1@4385.34,4199.63
L1_1: 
